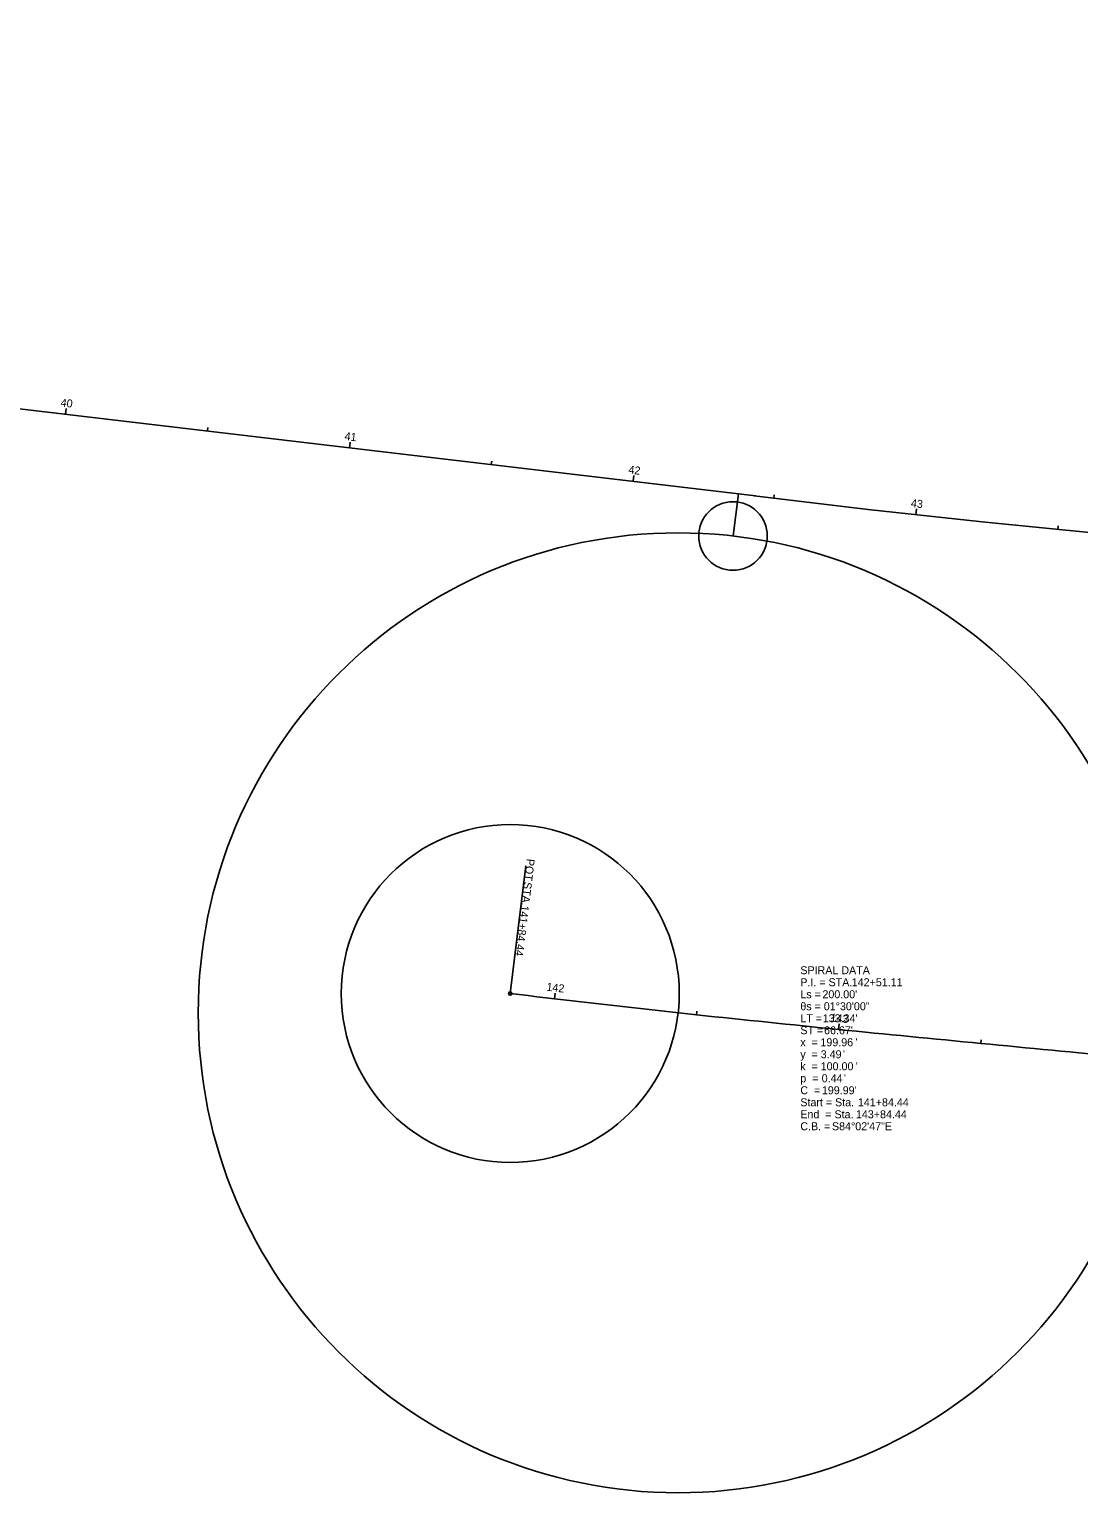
# Model space of a CAD drawing. Extents: x 2272920 to 2277360, y 743591 to 745058.
# Drawn here: x 2274048 to 2274415, y 743890 to 744402 of the extents above; entities that cross this region are included whole.
import ezdxf

# ---------------------------------------------------------------- set-up
doc = ezdxf.new("R2010")
doc.units = 0
for name, color, linetype in [('GE_X_Alignment', 7, 'Continuous'), ('GE_X_Alignment_100_Cardinal_Points', 7, 'Continuous'), ('GE_X_Alignment_100_Curve_Data', 7, 'Continuous'), ('GE_X_Alignment_100_Stations', 7, 'Continuous'), ('SC_Scratch1', 7, 'Continuous'), ('SC_Scratch3', 7, 'Continuous')]:
    doc.layers.add(name, color=color, linetype=linetype)

msp = doc.modelspace()

# ---------------------------------------------------------------- linework, layer by layer
at = {"layer": 'GE_X_Alignment'}
msp.add_line((2272920.72, 744401.68), (2274301.71, 744238.47), dxfattribs=at)
for points in [[(2274301.26, 744238.44), (2274341.09, 744233.66), (2274380.96, 744229.3), (2274420.88, 744225.35)], [(2274414.79, 744043.55), (2274454.73, 744039.73)]]:
    msp.add_lwpolyline(points, dxfattribs=at)
msp.add_open_spline([(2274215.87, 744064.29), (2274232.42, 744062.27), (2274265.53, 744058.43), (2274315.26, 744053.23), (2274365.01, 744048.28), (2274398.19, 744045.13), (2274414.79, 744043.55)], degree=3, dxfattribs=at)
at = {"layer": 'GE_X_Alignment_100_Cardinal_Points'}
msp.add_line((2274215.87, 744064.29), (2274221.32, 744108.96), dxfattribs=at)
msp.add_circle((2274215.87, 744064.29), 0.6, dxfattribs=at)
at = {"layer": 'GE_X_Alignment_100_Stations'}
for p, q in [((2274060.27, 744267.01), (2274060.51, 744268.99)), ((2274109.93, 744261.14), (2274110.07, 744262.33)), ((2274159.58, 744255.27), (2274159.81, 744257.26)), ((2274209.23, 744249.4), (2274209.38, 744250.59)), ((2274258.89, 744243.53), (2274259.12, 744245.52)), ((2274308.09, 744237.62), (2274308.23, 744238.81)), ((2274357.75, 744231.83), (2274357.97, 744233.82)), ((2274407.49, 744226.68), (2274407.61, 744227.87)), ((2274231.32, 744062.44), (2274231.55, 744064.42)), ((2274281.01, 744056.85), (2274281.14, 744058.05)), ((2274330.74, 744051.7), (2274330.94, 744053.69)), ((2274380.5, 744046.83), (2274380.62, 744048.02))]:
    msp.add_line(p, q, dxfattribs=at)
msp.add_open_spline([(2274215.87, 744064.29), (2274232.42, 744062.27), (2274265.53, 744058.43), (2274315.26, 744053.23), (2274365.01, 744048.28), (2274398.19, 744045.13), (2274414.79, 744043.55)], degree=3, dxfattribs=at)
at = {"layer": 'SC_Scratch1'}
for points in [[(2274301.26, 744238.44), (2274341.09, 744233.66), (2274380.96, 744229.3), (2274420.88, 744225.35)], [(2274414.79, 744043.55), (2274454.73, 744039.73)]]:
    msp.add_lwpolyline(points, dxfattribs=at)
at = {"layer": 'SC_Scratch3'}
msp.add_line((2274293.81, 744224.37), (2274295.68, 744239.18), dxfattribs=at)
for centre, radius in [((2274293.81, 744224.37), 12), ((2274274.61, 744057.53), 167.94), ((2274215.87, 744064.29), 59.13)]:
    msp.add_circle(centre, radius, dxfattribs=at)

# ---------------------------------------------------------------- texts
at = {"layer": 'GE_X_Alignment_100_Cardinal_Points'}
for s, p in [('POT', (2274221.67, 744111.55)), (' STA. ', (2274220.81, 744104.47)), ('141+84.44', (2274219.68, 744095.22))]:
    msp.add_text(s, height=2.8, rotation=263.0464, dxfattribs=at).set_placement(p)
at = {"layer": 'GE_X_Alignment_100_Curve_Data'}
for s, p in [('SPIRAL DATA', (2274317.36, 744071.02)), ('P.I. = STA. ', (2274317.36, 744066.82)), ('142+51.11', (2274335.35, 744066.82)), ('θs = ', (2274317.36, 744058.42)), ('Ls = ', (2274317.36, 744062.62)), ("200.00'", (2274325.1, 744062.62)), ('01°30\'00"', (2274325.57, 744058.42)), ('LT = ', (2274317.36, 744054.22)), ("133.34'", (2274325.21, 744054.22)), ('ST = ', (2274317.36, 744050.02)), ("66.67'", (2274325.66, 744050.02)), ('x  = ', (2274317.36, 744045.82)), ('199.96', (2274324.39, 744045.82)), ("'", (2274336.64, 744045.82)), ('y  = ', (2274317.36, 744041.62)), ('k  = ', (2274317.36, 744037.42)), ('3.49', (2274324.49, 744041.62)), ('100.00', (2274324.49, 744037.42)), ("'", (2274332.27, 744041.62)), ('p  = ', (2274317.36, 744033.22)), ('0.44', (2274324.84, 744033.22)), ("'", (2274332.62, 744033.22)), ("'", (2274336.74, 744037.42)), ('C  = ', (2274317.36, 744029.02)), ("199.99'", (2274324.91, 744029.02)), ('Start = Sta. ', (2274317.36, 744024.82)), ('141+84.44', (2274337.51, 744024.82)), ('End  = Sta. ', (2274317.36, 744020.62)), ('143+84.44', (2274336.82, 744020.62)), ('C.B. = ', (2274317.36, 744016.42)), ('S84°02\'47"E', (2274328.43, 744016.42))]:
    msp.add_text(s, height=2.8, dxfattribs=at).set_placement(p)
at = {"layer": 'GE_X_Alignment_100_Stations'}
for s, rotation, p in [('40', 353.2598, (2274058.43, 744269.74)), ('41', 353.2598, (2274157.78, 744258)), ('42', 353.2598, (2274257.1, 744246.26)), ('43', 353.7574, (2274355.96, 744234.55)), ('142', 353.2707, (2274228.42, 744065.3)), ('143', 354.279, (2274327.81, 744054.51))]:
    msp.add_text(s, height=2.8, rotation=rotation, dxfattribs=at).set_placement(p)

doc.saveas('drawing.dxf')
